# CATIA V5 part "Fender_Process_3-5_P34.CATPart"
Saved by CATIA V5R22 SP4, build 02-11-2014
Part number: Fender
Bounding box of the stored display mesh (mm): x -800 to 100, y -40 to 122.298, z 0 to 580
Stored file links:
  C:\DATA\Car_ASSY\教育モデル\3_SOL\Fender_Process_3-5_P34.CATPart
  C:\DATA\Car_ASSY\教育モデル\3_SOL\Car_Fender.CATPart
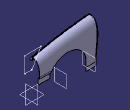
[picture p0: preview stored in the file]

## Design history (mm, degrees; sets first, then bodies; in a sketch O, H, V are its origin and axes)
Set1
  Plane1: type Offset, RefPlane yz-plane, Offset 400, reversed
  Plane2: type Offset, RefPlane Plane1, Offset 400, reversed
Body1 (main body)
Body2
  Sketch1 on yz-plane, origin (0, 0, 0), H (0, 1, 0), V (0, 0, 1)
    point P4 (100, 50)
    point P5 (10, 450)
    spline S1 through (10, 450) (100, 50)
    line L1 (0, 450) -> (10, 450)
    line L2 (0, 0) -> (0, 450)
    line L3 (100, 0) -> (0, 0)
    line L4 (100, 50) -> (100, 0)
    point P6 (100, 50)
    point P7 (10, 450)
    distance P4 L3 = 50
    distance P5 L2 = 10
    distance L4 L2 = 100
    distance L1 H = 450
    coincidence: L2 V, H L3, P4 P6, P7 P5
  Sketch2 on Plane1, origin (-400, 0, 0), H (0, 1, 0), V (0, 0, 1)
    point P4 (100, 50)
    point P5 (10, 530)
    spline S1 through (10, 530) (100, 50)
    line L1 (0, 530) -> (10, 530)
    line L2 (0, 0) -> (0, 530)
    line L3 (100, 0) -> (0, 0)
    line L4 (100, 50) -> (100, 0)
    point P6 (100, 50)
    point P7 (10, 530)
    distance P4 L3 = 50
    distance P5 L2 = 10
    distance L4 L2 = 100
    distance L1 H = 530
    coincidence: L2 V, H L3, P4 P6, P7 P5
  Sketch3 on Plane2, origin (-800, 0, 0), H (0, 1, 0), V (0, 0, 1)
    point P4 (100, 50)
    point P5 (10, 580)
    spline S1 through (10, 580) (100, 50)
    line L1 (0, 580) -> (10, 580)
    line L2 (0, 0) -> (0, 580)
    line L3 (100, 0) -> (0, 0)
    line L4 (100, 50) -> (100, 0)
    point P6 (100, 50)
    point P7 (10, 580)
    distance P4 L3 = 50
    distance P5 L2 = 10
    distance L4 L2 = 100
    distance L1 H = 580
    coincidence: L2 V, H L3, P4 P6, P7 P5
  Loft1: solid, Sections (Sketch1; Sketch2; Sketch3)
  Body3
    Sketch4 on zx-plane, origin (0, 0, 0), H (-1, 0, 0), V (0, 0, 1)
      line L1 (-46.4952, 240) -> (159.0779, 240)
      arc A1 centre (390, 110) radius 265 from (159.0779, 240) to (655, 109.9999) cw
      point P2 (390, 110)
      line L2 (655, 109.9999) -> (655, -30)
      line L3 (-46.4952, 626.6258) -> (850, 626.6258)
      line L4 (850, 626.6258) -> (850, -30)
      line L5 (850, -30) -> (655, -30)
      line L6 (-46.4952, 626.6258) -> (-46.4952, 240)
      radius A1 = 265
      distance P2 H = 110
      distance V P2 = 390
      distance H L1 = 240
      horizontal: L1 H, L3 H, L5 H
      tangency: L2 A1
      vertical: L2 V, L4 V, L6 V
    Pad1: profile Sketch4, direction (0, 1, 0), length 340, mirrored extent
  Intersect1: tool Body3
  Shell1: ExtOffset 0, Face (face of Loft1; face of Loft1; face of Pad1 from Sketch4.A1; face of Pad1 from Sketch4.L1; face of Loft1; face of Loft1), IntOffset 3
  Sketch5 on Plane2, origin (-800, 0, 0), H (0, 1, 0), V (0, 0, 1)
    line L1 (0, 580) -> (0, 545)
    line L2 (-5, 540) -> (-40, 540)
    point P2 (-40, 540)
    reference projected line E1 (10, 580) -> (0, 580)
    reference intersected line E2 (0, 0) -> (0, 580)
    arc A1 centre (-5, 545) radius 5 from (-5, 540) to (0, 545) ccw
    line L3 (-5, 537) -> (-40, 537)
    arc A2 centre (-5, 545) radius 8 from (-5, 537) to (3, 545) ccw
    line L4 (3, 580) -> (3, 545)
    line L5 (-40, 537) -> (-40, 540)
    line L6 (3, 580) -> (0, 580)
    reference projected line E3 (10, 580) -> (0, 580)
    distance E1 L2 = 40
    radius A1 = 5
    distance L1 P2 = 40
    length L5 = 3
    length L6 = 3
    radius A2 = 8
    vertical: L1 V, L4 V, L5 V
    horizontal: L2 H, L6 H, L3 H
    coincidence: L1 E2, L6 E3
    tangency: A1 L2, A1 L1, L4 A2, A2 L3
  Rib1: profile Sketch5, centre curve edge [face of Loft1 | face of Loft1]
  Sketch6 on Plane2, origin (-800, 0, 0), H (0, 1, 0), V (0, 0, 1)
    projected curve E1
    projected line E2 (10, 576.9862) -> (3, 576.9862)
    point P4 (3, 576.9862)
    projected line E3 (3, 576.9862) -> (3, 545)
    projected line E4 (3, 576.9862) -> (3, 399.233)
    point P5 (3, 576.9862)
    projected line E5 (97, 0) -> (97, 50)
    line L1 (97, 0) -> (37, 0)
    line L2 (37, 0) -> (17.9077, 155.4943)
    arc A1 centre (2003, 399.233) radius 2000 from (3, 399.233) to (17.9077, 155.4943) ccw
    angle L1 L2 = 97
    length L1 = 60
    radius A1 = 2000
    horizontal: L1 H
    tangency: A1 E3, A1 L2
    coincidence: P4 P5
  Pad2: profile Sketch6, direction (1, 0, 0), length 10, opposite side length -7
  Sketch7 on yz-plane, origin (0, 0, 0), H (0, 1, 0), V (0, 0, 1)
    projected curve E1
    projected curve E2
    point P1 (103.8705, 240)
    line L1 (100.927, 243) -> (92.1161, 243)
    line L2 (86.1161, 237) -> (86.1161, 160)
    line L3 (86.1161, 160) -> (89.1161, 160)
    line L4 (89.1161, 160) -> (89.1161, 237)
    point P5 (103.8705, 240)
    line L5 (101.1109, 260) -> (104.111, 260)
    point P6 (101.1109, 260)
    point P7 (104.111, 260)
    offset curve E3
    offset curve E4
    line L6 (92.1161, 240) -> (103.8705, 240)
    arc A1 centre (92.1161, 237) radius 3 from (92.1161, 240) to (89.1161, 237) ccw
    arc A2 centre (92.1161, 237) radius 6 from (92.1161, 243) to (86.1161, 237) ccw
    distance L4 L2 = 3
    distance L4 E1 = 15
    distance L1 L6 = 3
    radius A1 = 3
    radius A2 = 6
    distance L6 L3 = 80
    distance L5 L6 = 20
    horizontal: L1 H, L3 H, L5 H, L6 H
    vertical: L2 V, L4 V
    coincidence: P7 E1, E3 P6, P6 L5, P7 L5, P5 P1
    tangency: A1 L6, A1 L4, A2 L1, A2 L2
  Rib2: profile Sketch7, centre curve edge [face of Pad1 from Sketch4.L1 | face of Shell1]
Body4
  Sketch8 on zx-plane, origin (0, 0, 0), H (-1, 0, 0), V (0, 0, 1)
    point P1 (0, 300)
    line L1 (0, 300) -> (127.0171, 520)
    line L2 (127.0171, 520) -> (-100, 520)
    line L3 (-100, 520) -> (-100, 300)
    line L4 (-100, 300) -> (0, 300)
    angle L1 L4 = 120
    distance L4 H = 300
    coincidence: P1 V
    horizontal: L2 H, L4 H
    vertical: L3 V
